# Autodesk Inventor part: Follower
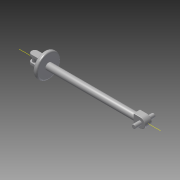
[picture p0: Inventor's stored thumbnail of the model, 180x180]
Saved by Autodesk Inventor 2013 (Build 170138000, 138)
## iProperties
Created: 2008-06
Part Number: Follower
Document SubType Name: Modeling
Designer: tangg
Density: 7.85 g/cm^3
Mass: 2.02034 g
Surface Area: 17.8273 cm^2
Volume: 2.02034 cm^3
Stock Number: Follower
Material: Alloy Steel
Author: tangg
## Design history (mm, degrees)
sketch "Sketch1"
  geometry: L1 (0, 3.75)-(-82.55, 3.75); L2 (-82.55, 3.75)-(-82.55, -3.75); L3 (-82.55, -3.75)-(0, -3.75); L4 (0, -3.75)-(0, 3.75); 2 further points
  constraints: 8 end point, 3 perpendicular, 1 coincident, 1 midpoint, 1 vertical, 1 vertical alignment, 2 other
  dimensions: "d0" = 7.5 distance of L3.end L1.start; "d1" = 82.55 distance of L2.end L3.end
extrude "Extrusion1" new body sketch "Sketch1" stored distance "d2" = 5.08; taper "d3" = 0 deg
workplane "Work Plane4"
sketch "Sketch16"
  geometry: L1 (3.75, 2.54)-(3.75, -2.54) reference; L2 (3.75, -2.54)-(-3.75, -2.54) reference; L3 (-3.75, -2.54)-(-3.75, 2.54) reference; L4 (-3.75, 2.54)-(3.75, 2.54) reference; C1 r 2.54 at (0, 0); 1 further point
  constraints: 1 centre point, 1 coincident
  dimensions: "d28" = 5.08 diameter of C1
extrude "Extrusion11" cut sketch "Sketch16" distance "d29" = 69.85; taper "d30" = 0 deg
sketch "Sketch2"
  geometry: C1 r 1.5 at (0, 0); 1 further point
  constraints: 1 centre point, 1 coincident
  dimensions: "d32" = 3 diameter of C1
extrude "Extrusion2" join sketch "Sketch2" stored distance "d4" = 15.24; taper "d5" = 0 deg
sketch "Sketch11"
  geometry: L1 (82.55, -2.54)-(82.55, 2.54) reference; L2 (82.55, -2.54)-(82.55, 2.54) reference; C1 r 2.54 at (82.55, 0); 2 further points
  constraints: 1 centre point, 1 coincident, 1 midpoint
extrude "Extrusion7" join sketch "Sketch11" stored distance "d18" = 7.5; taper "d19" = 0 deg
sketch "Sketch12"
  geometry: L1 (5.08, -2.54)-(0, -2.54) reference; C1 r 4.763 at (82.55, 0); A1 r 2.54 centre (82.55, 0) between (82.55, -2.54) and (82.55, 2.54) reference; A2 r 2.54 centre (82.55, 0) between (82.55, -2.54) and (82.55, 2.54) reference; 2 further points
  constraints: 1 centre point, 1 coincident
extrude "Extrusion8" cut sketch "Sketch12" stored distance "d20" = 3.81; taper "d21" = 0 deg
sketch "Sketch15"
  geometry: C1 r 1.587 at (82.55, 0); A1 r 2.54 centre (82.55, 0) between (82.55, -2.54) and (82.55, 2.54) reference; 3 further points
  constraints: 1 centre point, 1 coincident
extrude "Extrusion10" join sketch "Sketch15" stored distance "d24" = 5.08; taper "d25" = 0 deg
fillet "Fillet2" dims "d26" = 0.3175
sketch "Sketch17"
  geometry: C1 r 9 at (0, 0); 1 further point
  constraints: 1 centre point, 1 coincident
  dimensions: "d36" = 18 diameter of C1
extrude "Extrusion12" join sketch "Sketch17" distance "d33" = 3; taper "d34" = 0 deg
fillet "Fillet4" dims "d35" = 1
body "Solid1"
node "Projected Loop3"
node "Projected Loop4"
node "Project Cut Edges1"
other parameters: "d27" = -5.08
